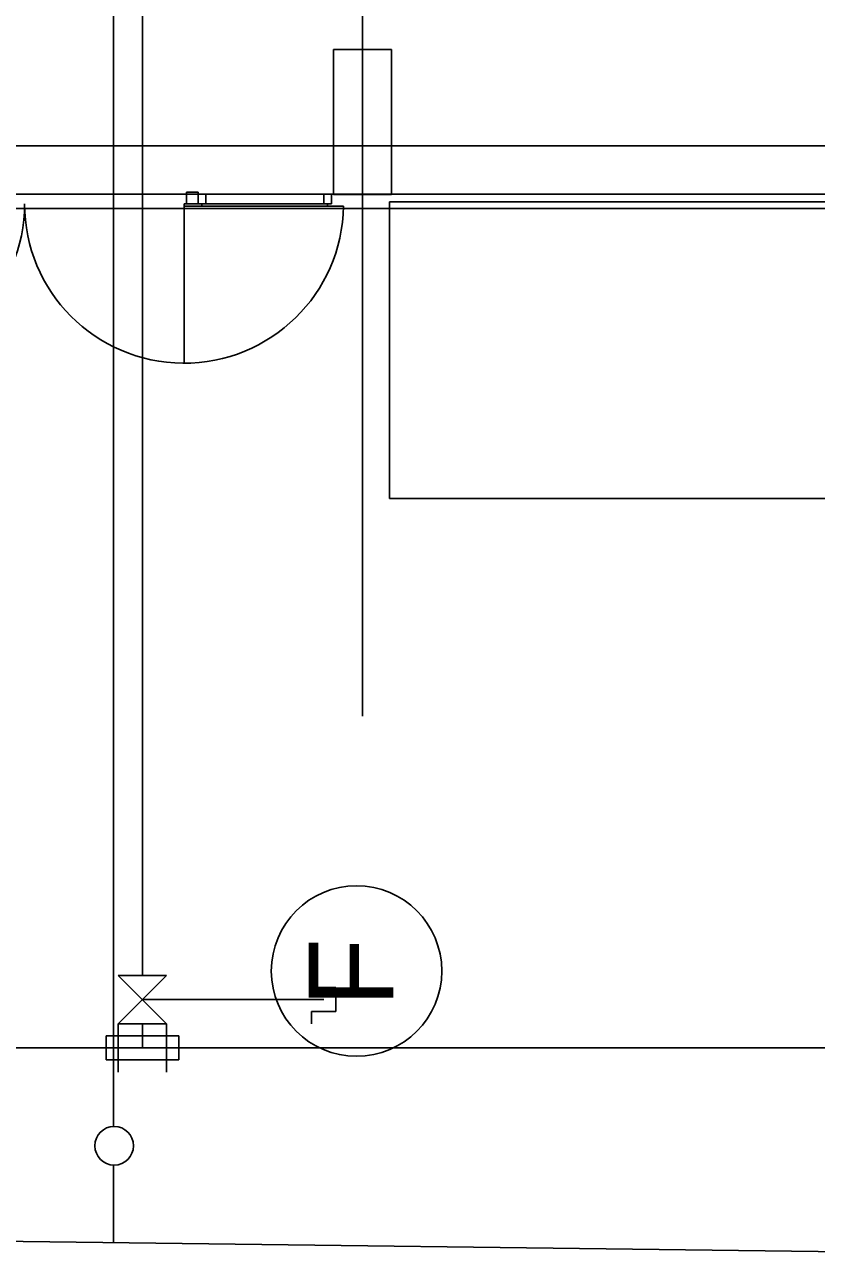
# Model space of a CAD drawing. Extents: x -264031 to -263588, y -1242281 to -1242059.
# Drawn here: x -263887.96 to -263879.77, y -1242252.28 to -1242239.55 of the extents above; entities that cross this region are included whole.
import ezdxf

# ---------------------------------------------------------------- set-up
doc = ezdxf.new("R2010")
doc.units = 0
for name, color, linetype in [('HESCON_OSI_STAVBY_KFA', 7, 'Continuous'), ('KFA_2D_SITUACIA_DSP', 7, 'Continuous'), ('KFA_JESTV_IS_DSP_-_KANAL_SPLASK', 7, 'Continuous')]:
    doc.layers.add(name, color=color, linetype=linetype)

msp = doc.modelspace()

# ---------------------------------------------------------------- linework, layer by layer
at = {"layer": 'HESCON_OSI_STAVBY_KFA'}
for p, q in [((-263884.468, -1242083.237), (-263884.468, -1242246.707)), ((-263792.653, -1242240.807), (-263911.523, -1242240.807))]:
    msp.add_line(p, q, dxfattribs=at)
msp.add_circle((-263884.528, -1242249.345), 0.882, dxfattribs=at)
at = {"layer": 'KFA_2D_SITUACIA_DSP'}
for p, q in [((-263887.043, -1242235.757), (-263887.043, -1242250.954)), ((-263886.743, -1242249.39), (-263886.743, -1242235.757)), ((-263884.768, -1242241.312), (-263884.768, -1242239.812)), ((-263884.768, -1242239.812), (-263884.168, -1242239.812)), ((-263884.168, -1242239.812), (-263884.168, -1242241.312)), ((-263894.581, -1242241.307), (-263809.355, -1242241.307)), ((-263886.288, -1242241.407), (-263886.288, -1242241.287)), ((-263886.288, -1242241.287), (-263886.168, -1242241.287)), ((-263886.168, -1242241.287), (-263886.168, -1242241.407)), ((-263886.088, -1242241.307), (-263886.168, -1242241.307)), ((-263886.168, -1242241.307), (-263886.168, -1242241.407)), ((-263886.088, -1242241.407), (-263886.088, -1242241.307)), ((-263884.868, -1242241.407), (-263884.868, -1242241.307)), ((-263884.868, -1242241.307), (-263884.788, -1242241.307)), ((-263884.788, -1242241.307), (-263884.788, -1242241.407)), ((-263884.168, -1242241.312), (-263884.768, -1242241.312)), ((-263886.288, -1242241.407), (-263886.313, -1242241.407)), ((-263886.313, -1242241.407), (-263886.313, -1242243.057)), ((-263884.663, -1242241.432), (-263886.313, -1242241.432)), ((-263886.168, -1242241.407), (-263886.288, -1242241.407)), ((-263886.168, -1242241.407), (-263886.128, -1242241.407)), ((-263884.828, -1242241.407), (-263886.128, -1242241.407)), ((-263886.128, -1242241.407), (-263886.128, -1242241.432)), ((-263886.128, -1242241.407), (-263886.088, -1242241.407)), ((-263886.128, -1242241.432), (-263884.828, -1242241.432)), ((-263884.828, -1242241.407), (-263884.868, -1242241.407)), ((-263884.828, -1242241.432), (-263884.828, -1242241.407)), ((-263884.788, -1242241.407), (-263884.828, -1242241.407)), ((-263884.188, -1242244.458), (-263884.188, -1242241.388)), ((-263884.188, -1242241.388), (-263876.738, -1242241.388)), ((-263876.738, -1242244.458), (-263884.188, -1242244.458)), ((-263886.493, -1242249.39), (-263886.993, -1242249.39)), ((-263886.993, -1242249.89), (-263886.493, -1242249.39)), ((-263886.993, -1242249.39), (-263886.493, -1242249.89)), ((-263884.993, -1242249.515), (-263884.993, -1242249.39)), ((-263884.743, -1242249.515), (-263884.993, -1242249.515)), ((-263884.743, -1242249.765), (-263884.743, -1242249.515)), ((-263886.743, -1242249.64), (-263884.868, -1242249.64)), ((-263884.993, -1242249.765), (-263884.993, -1242249.89)), ((-263884.993, -1242249.765), (-263884.743, -1242249.765)), ((-263886.493, -1242249.89), (-263886.993, -1242249.89)), ((-263886.993, -1242249.89), (-263886.993, -1242250.39)), ((-263886.743, -1242250.14), (-263886.743, -1242249.89)), ((-263886.743, -1242249.89), (-263886.743, -1242250.14)), ((-263886.493, -1242249.89), (-263886.493, -1242250.39)), ((-263886.368, -1242250.015), (-263887.118, -1242250.015)), ((-263887.118, -1242250.015), (-263887.118, -1242250.265)), ((-263886.368, -1242250.265), (-263886.368, -1242250.015)), ((-263924.143, -1242250.14), (-263788.143, -1242250.14)), ((-263887.118, -1242250.265), (-263886.368, -1242250.265)), ((-263887.043, -1242251.353), (-263887.043, -1242252.153))]:
    msp.add_line(p, q, dxfattribs=at)
msp.add_lwpolyline([(-263794.893, -1242227.382), (-263808.968, -1242241.457), (-263894.968, -1242241.457), (-263909.043, -1242227.382), (-263909.043, -1242196.333), (-263914.143, -1242196.333), (-263914.143, -1242132.433), (-263909.043, -1242132.433), (-263909.043, -1242101.382), (-263894.968, -1242087.307), (-263808.968, -1242087.307), (-263794.893, -1242101.382), (-263794.893, -1242227.382)], dxfattribs=at)
msp.add_circle((-263887.036, -1242251.153), 0.2, dxfattribs=at)
for centre, start, end in [((-263889.613, -1242241.407), 180.8682, 0), ((-263886.313, -1242241.407), 180, 359.1318)]:
    msp.add_arc(centre, 1.65, start, end, dxfattribs=at)
at = {"layer": 'KFA_JESTV_IS_DSP_-_KANAL_SPLASK'}
msp.add_line((-263877.504, -1242252.277), (-263922.041, -1242251.701), dxfattribs=at)

# ---------------------------------------------------------------- texts
at = {"layer": 'HESCON_OSI_STAVBY_KFA'}
msp.add_text('F', height=0.875, rotation=90, dxfattribs=at).set_placement((-263884.147, -1242249.718))

doc.saveas('drawing.dxf')
